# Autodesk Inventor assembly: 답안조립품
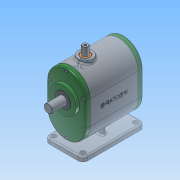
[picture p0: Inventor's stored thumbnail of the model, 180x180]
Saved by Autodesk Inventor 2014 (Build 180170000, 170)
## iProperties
Created: 2016-12
Part Number: 답안조립품
Document SubType Name: Assembly
Designer: NET
Author: NET
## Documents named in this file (14)
- C:\Users\NET\Desktop\361207V1015\답안조립품.iam
- C:\Users\NET\Desktop\361207V1015\본체.ipt
- C:\Users\NET\Desktop\361207V1015\뒤커버.ipt
- C:\Users\NET\Desktop\361207V1015\메인축.ipt
- C:\Users\NET\Desktop\361207V1015\베어링 608.ipt
- C:\Users\NET\Desktop\361207V1015\베어링 6003.ipt
- C:\Users\NET\Desktop\361207V1015\볼트 M4.ipt
- C:\Users\NET\Desktop\361207V1015\부시.ipt
- C:\Users\NET\Desktop\361207V1015\서브축.ipt
- C:\Users\NET\Desktop\361207V1015\슬라이더.ipt
- C:\Users\NET\Desktop\361207V1015\앞커버.ipt
- C:\Users\NET\Desktop\361207V1015\오일실 8 22 7.ipt
- C:\Users\NET\Desktop\361207V1015\오일실 17 32 8.ipt
- C:\Users\NET\Desktop\361207V1015\가변스프링.ipt
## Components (1 placed, 1 different names)
1. 가변스프링:1
